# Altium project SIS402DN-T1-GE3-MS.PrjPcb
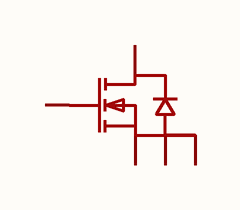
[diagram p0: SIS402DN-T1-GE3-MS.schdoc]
1 sheet, 1 parts. Net scope: global (net labels, ports and power ports of the same name join across sheets).

## Sheet SIS402DN-T1-GE3-MS.schdoc
size 127 x 101 mm

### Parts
Q?  sis402dn-t1-ge3-ms  [DFN-8_L3.3-W3.3-P0.65-BL]  (value not drawn)

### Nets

Not connected (* = marked no-connect by the designer): Q? 1(S) 2(S) 3(S) 4(G) 5(D)

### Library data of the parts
Q? = sis402dn-t1-ge3-ms: 数量:1个N沟道;漏源电压(Vdss):30V;连续漏极电流(Id):60A;导通电阻(RDS(on)):4mΩ@10V;耗散功率(Pd):62.5W;阈值电压(Vgs(th)):1V;; Manufacturer: MSKSEMI(美森科); AddInBom: yes; ModelId: f0059a17dd8f409ba5a4c367eb8306e1; ModelTransform: 129.921,129.99974,0,0,0,0,0.002,31.498,0; Number: 1个N沟道; Drain to Source Voltage: 30V; Current - Continuous Drain(Id): 60A; Pd - Power Dissipation: 62.5W; Gate Threshold Voltage (Vgs(th)): 1V; Gate Charge(Qg): 31.6nC; Input Capacitance(Ciss): 3.075nF; Reverse Transfer Capacitance (Crss@Vds): 315pF; Configuration: 独立式; Type: N沟道; Output Capacitance(Coss): 400pF; Vgs: ±20V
